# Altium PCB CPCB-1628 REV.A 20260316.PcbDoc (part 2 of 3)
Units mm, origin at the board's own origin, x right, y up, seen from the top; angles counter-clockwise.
Board outline 103 x 58.8 mm, 4 copper layers (Top Layer 1, Layer1, Layer2, Bottom Layer 1), stack 0.603 mm thick; 176 components, 137 nets, 518 pads, 340 vias.
Unrouted connection lines stored in the file: 10.
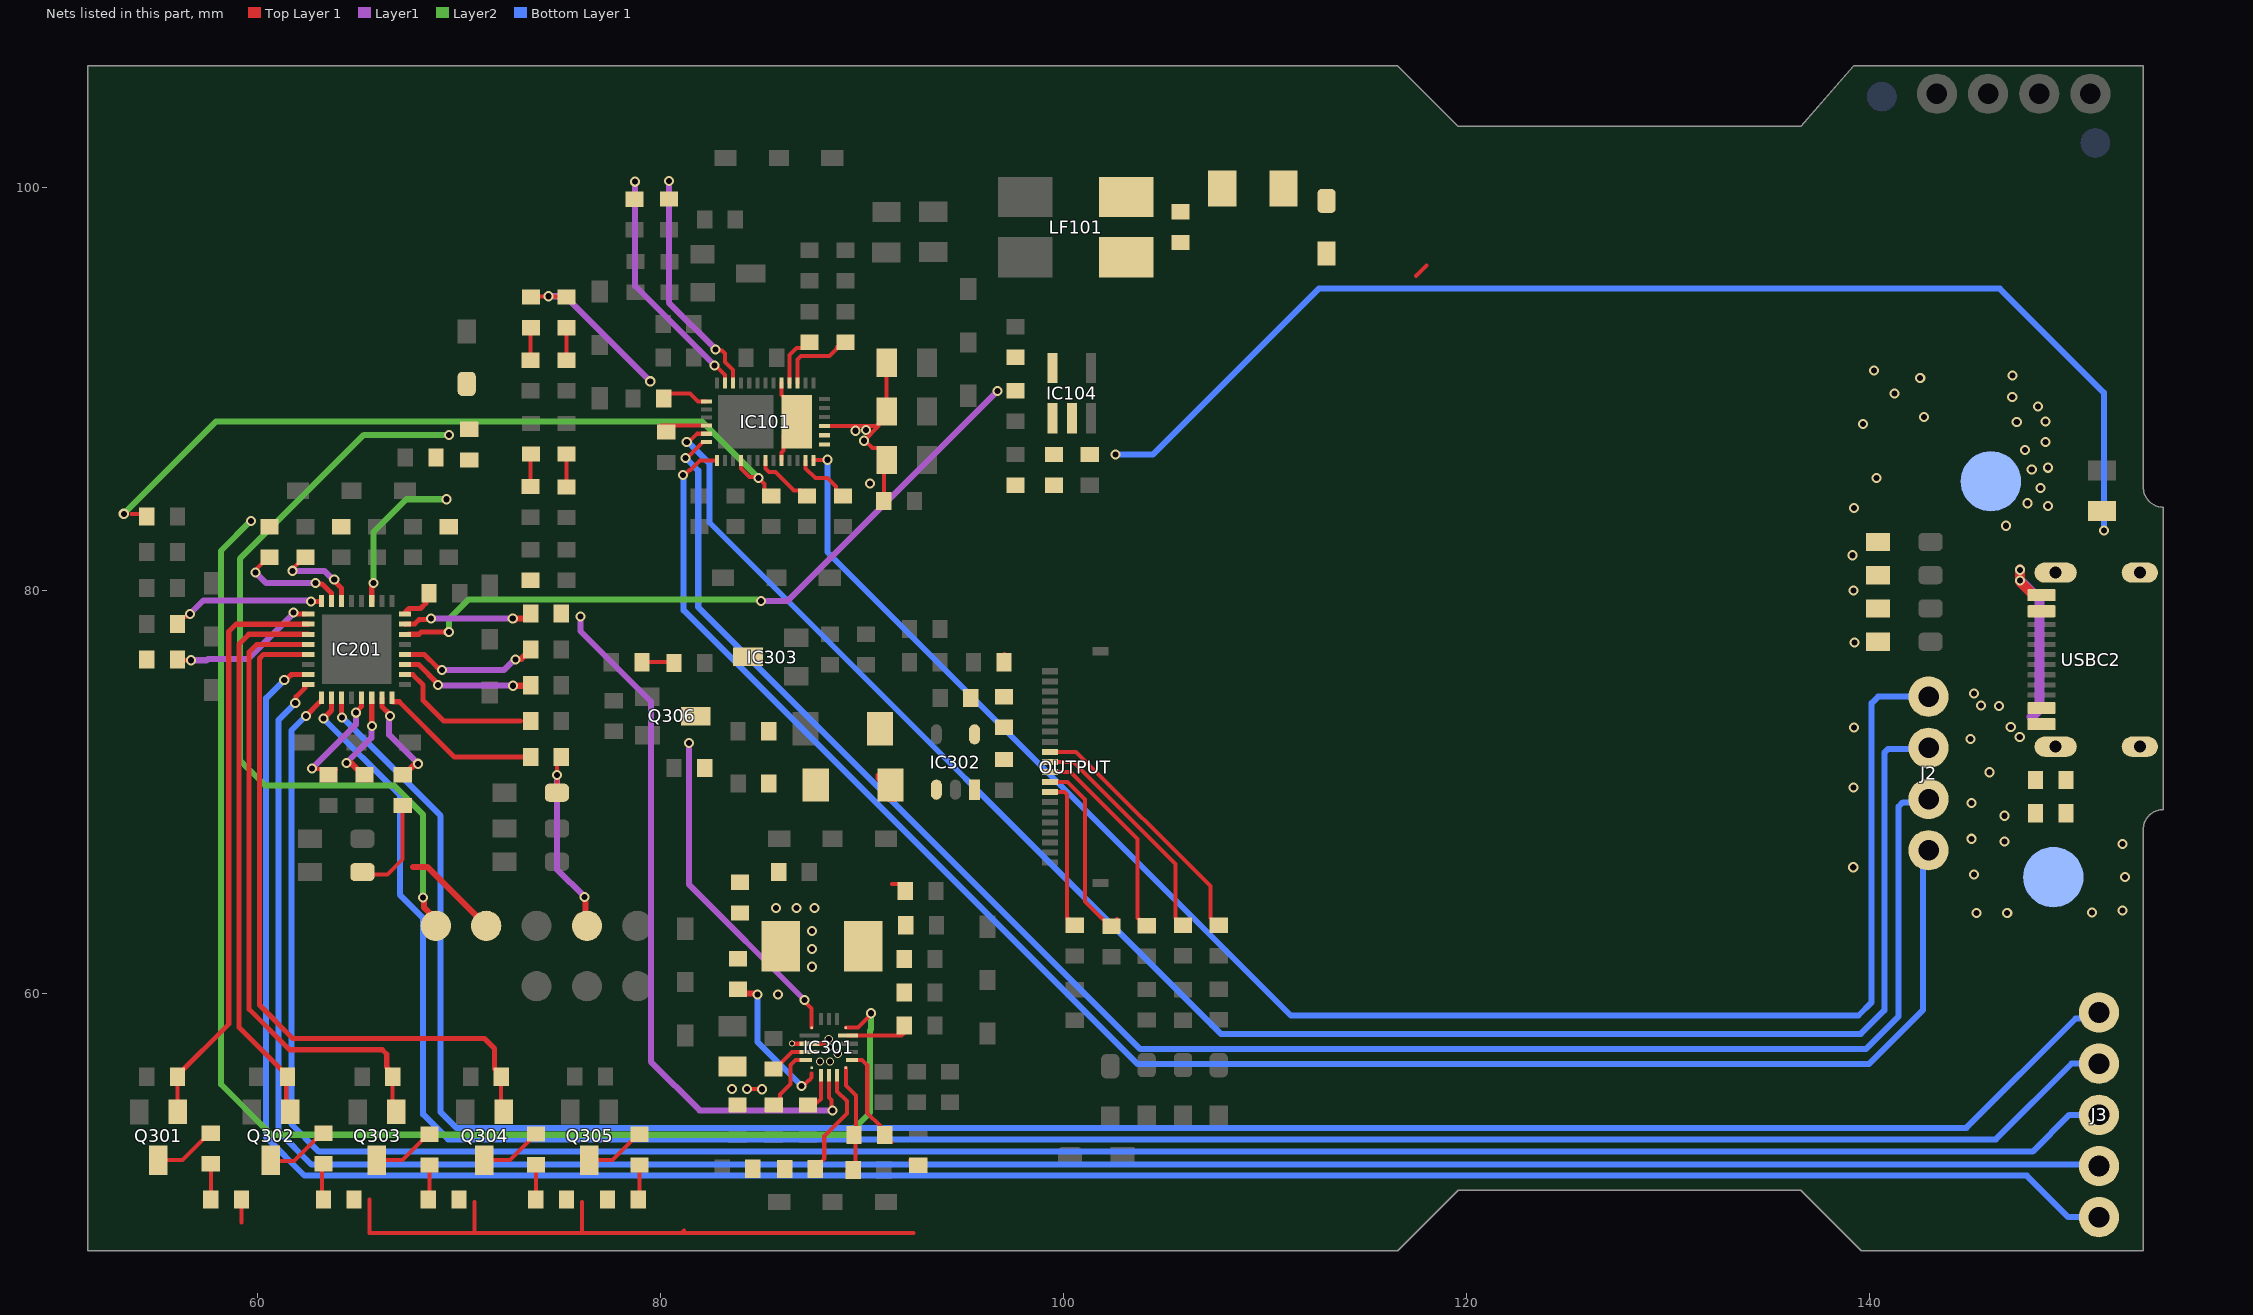
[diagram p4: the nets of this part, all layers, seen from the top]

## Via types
v1: diameter 0.5, hole 0.3, Top Layer 1 to Bottom Layer 1, 334 vias
v2: diameter 0.4, hole 0.3, Top Layer 1 to Bottom Layer 1, 5 vias
v3: diameter 0.3, hole 0.2, Top Layer 1 to Bottom Layer 1, 1 vias

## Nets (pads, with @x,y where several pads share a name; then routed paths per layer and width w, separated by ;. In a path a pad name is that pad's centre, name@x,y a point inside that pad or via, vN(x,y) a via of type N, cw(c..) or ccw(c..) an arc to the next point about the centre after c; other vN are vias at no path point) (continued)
INT_TPS25751D: IC101.10 R103.1 R231.1 R234.2 | length 38
  Top Layer 1 w0.2: 53.721,83.82 R231.1@54.61,83.82 ; IC101.10@83.981,86.467 83.981,86.292 83.981,86.068 84.393,85.655 84.779,85.655 v1(84.836,85.598) 85.126,85.308 85.126,84.987 85.279,84.834 R103.1@85.471,84.834
  Layer2 w0.3: v1(53.34,83.82) 57.912,88.392 82.042,88.392 v1(84.836,85.598)
LDO-1V5: C109.1 IC101.4 | length 2.2
  Top Layer 1 w0.2: C109.1@80.01,88.192 IC101.4@82.256,88.192
LDO-3V3: C108.1 IC101.1 R105.2 R109.2 | length 11.4
  Top Layer 1 w0.2: R105.2@73.533,94.615 v1(74.422,94.615) 75.311,94.615 R109.2@75.591,94.335 ; C108.1@80.135,89.535 80.389,89.789 81.432,89.789 81.829,89.392 IC101.1@82.256,89.392
  Layer1 w0.3: v1(74.422,94.615) 75.248,94.615 v1(79.467,90.396)
LED_GREEN1: IC101.5 J2.2 | length 89.6
  Top Layer 1 w0.2: v1(81.28,87.376) 81.361,87.376 81.777,87.792 IC101.5@82.256,87.792
  Bottom Layer 1 w0.2: v1(81.28,87.376) v1@81.358,87.376
  Bottom Layer 1 w0.3: v1@81.358,87.376 82.403,86.331 82.403,85.911 82.407,85.907 82.407,83.388 107.785,58.01 139.544,58.01 140.716,59.182 140.716,71.96 140.892,72.136 J2.2@142.539,72.136
LED_GREEN2: IC101.6 J2.3 | length 90.5
  Top Layer 1 w0.2: v1(81.218,86.591) 81.28,86.591 82.081,87.392 IC101.6@82.256,87.392
  Bottom Layer 1 w0.2: 81.903,85.598 81.903,85.698
  Bottom Layer 1 w0.3: v1(81.218,86.591) 81.849,85.96 81.849,85.598 81.849,79.187 103.787,57.249 139.799,57.249 141.427,58.877 141.427,69.291 141.634,69.498 142.745,69.498 J2.3@142.909,69.662
LED_GREEN3: IC101.7 J2.4 | length 88.7
  Top Layer 1 w0.2: v1(81.099,85.742) 81.181,85.742 81.425,85.987 81.468,85.987 81.948,86.467 IC101.7@82.781,86.467
  Bottom Layer 1 w0.3: v1(81.099,85.742) 81.128,85.714 81.128,79.033 103.656,56.505 139.944,56.505 142.636,59.197 142.636,66.85 J2.4@142.909,67.122
LED_GREEN4: IC101.19 J2.1 | length 84.7
  Top Layer 1 w0.2: IC101.19@87.581,86.467 87.581,86.484 88.249,86.484 v1(88.266,86.501)
  Bottom Layer 1 w0.3: v1(88.266,86.501) 88.266,81.914 111.259,58.921 139.433,58.921 140.081,59.569 140.081,74.422 140.401,74.742 J2.1@142.909,74.742
LED_GREEN5: 
LED_GREEN6: 
LED_RED1: IC201.15 J3.5 | length 117
  Top Layer 1 w0.2: IC201.15@62.495,75.837 IC201.15@62.497,75.839
  Top Layer 1 w0.254: v1(61.303,75.567) 61.369,75.567 61.633,75.831 61.674,75.831 61.682,75.839 62.494,75.839 IC201.15@62.495,75.837
  Bottom Layer 1 w0.3: v1(61.303,75.567) 60.409,74.674 60.409,52.875 62.31,50.974 147.781,50.974 149.845,48.91 J3.5@151.367,48.91
LED_RED2: IC201.16 J3.4 | length 114
  Top Layer 1 w0.254: v1(61.849,74.422) 61.896,74.469 61.896,74.738 62.324,75.166 62.324,75.337 62.326,75.339 IC201.16@62.497,75.339
  Bottom Layer 1 w0.3: v1(61.849,74.422) 61.022,73.595 61.022,53.151 62.645,51.528 151.224,51.528 J3.4@151.367,51.384
LED_RED3: IC201.17 J3.3 | length 112.8
  Top Layer 1 w0.2: IC201.17@63.147,74.514 IC201.17@63.147,74.689
  Top Layer 1 w0.254: v1(62.38,73.786) 63.109,74.514 IC201.17@63.147,74.514
  Bottom Layer 1 w0.3: v1(62.38,73.786) 61.662,73.067 61.662,53.527 63.023,52.166 148.074,52.166 149.899,53.991 J3.3@151.367,53.99
LED_RED4: IC201.18 J3.2 | length 108.1
  Top Layer 1 w0.254: v1(63.246,73.66) 63.647,74.061 IC201.18@63.647,74.689
  Bottom Layer 1 w0.3: v1(63.246,73.66) 67.037,69.869 67.037,64.916 68.199,63.754 68.199,54.013 69.438,52.773 146.245,52.773 150.002,56.53 J3.2@151.367,56.53
LED_RED5: 
LED_RED6: 
LED_WHITE: IC201.19 J3.1 | length 107.6
  Top Layer 1 w0.2: v1@64.15,73.739 v1(64.172,73.716)
  Top Layer 1 w0.254: v1@64.15,73.739 IC201.19@64.15,74.686
  Bottom Layer 1 w0.3: v1(64.172,73.716) 69.065,68.824 69.065,54.125 69.85,53.34 144.78,53.34 150.214,58.774 151.071,58.774 J3.1@151.367,59.07
NetC104_1: C104.1 C105.1 USBC2.1 USBC2.2 USBC2.3 USBC2.4
NetC116_1: C116.1 IC104.5
NetC201_1: 
NetC202_1: 
NetC203_1: 
NetC204_1: 
NetC205_1: 
NetC206_1: 
NetC207_1: 
NetC208_1: 
NetC209_1: 
NetC210_1: 
NetC211_1: 
NetC212_1: 
NetC216_2: C216.2 IC201.32 | length 1.8
  Top Layer 1 w0.254: IC201.32@67.319,78.951 67.49,79.121 68.072,79.121 68.329,79.378 68.329,79.63 C216.2@68.582,79.883
NetC303_1: C303.1 C304.1 IC301.17 | length 2.1
  Top Layer 1 w0.2: C304.1@85.707,56.263 85.707,56.32 85.93,56.543 85.936,56.543 86.511,57.118 IC301.17@87.377,57.118
NetC305_1: C305.1 IC301.1 | length 7.4
  Top Layer 1 w0.2: v1(86.976,55.424) 87.057,55.424 87.358,55.725 87.36,55.725 87.477,55.843 87.477,56.036
  Top Layer 1 w0.3: C305.1@83.827,60.218 84.045,60.001 84.747,60.001 v1(84.785,59.963)
  Bottom Layer 1 w0.3: v1(84.785,59.963) 84.785,57.615 v1(86.976,55.424)
NetC305_2: C305.2 IC301.16 L301.1 R306.2 | length 1.8
  Top Layer 1 w0.2: v3@86.611,57.518 88.12,57.518 88.288,57.349 v2(88.329,57.349)
  other v1: 85.811,59.963 87.503,61.341 87.485,62.23 87.485,63.119 85.707,64.262 86.723,64.262 87.612,64.262
  other v2: 87.884,56.642 88.392,56.642 88.773,57.023 88.327,57.758
  other v3: 86.502,57.528
NetC306_1: C306.1 IC301.2 | length 1.9
  Top Layer 1 w0.2: C306.1@87.243,54.597 87.751,54.597 87.934,54.78 IC301.2@87.934,55.955
NetC307_2: C307.2 R306.1
NetC319_1: C319.1 C320.2 D301.2 D302.2 IC303.3 | length 0.2
  Top Layer 1 w0.2: C319.1@85.456,73.029 C319.1@85.469,73.016 ; D301.2@87.374,70.174 D301.2@87.374,70.349
NetF101_1: F101.1 pad.1@146.001,85.434 USBC2.A4B9 USBC2.B4A9 ZD1.2
  other v1: 146.408,74.284 145.51,74.316 145.164,74.894 146.747,83.226 148.844,84.201 147.817,84.344 148.463,85.09 148.03,86.009 148.844,86.106 147.701,86.995 148.717,87.376 147.284,88.376 148.717,88.392 148.336,89.154 147.063,89.623 147.066,90.678
NetIC101_13: IC101.13 R115.2 | length 3
  Top Layer 1 w0.2: IC101.13@85.181,86.467 85.181,86.068 85.357,85.892 85.685,85.892 86.59,84.987 86.969,84.987 R115.2@87.249,84.707
NetIC101_15: IC101.0@86.741,88.392 IC101.15 IC101.30 | length 4.5
  Top Layer 1 w0.2: IC101.15@85.981,86.467 85.981,86.866 86.076,86.961 86.076,87.727 IC101.0@86.741,88.392 86.741,88.952 85.981,89.712 IC101.30@85.981,90.317
NetIC101_18: IC101.18 R104.1 | length 2.9
  Top Layer 1 w0.2: IC101.18@87.181,86.467 87.181,86.068 87.658,85.591 88.27,85.591 88.677,85.184 88.677,84.987 88.83,84.834 R104.1@89.027,84.834
NetIC101_28: IC101.28 R116.2 | length 3.9
  Top Layer 1 w0.2: IC101.28@86.781,90.317 86.781,91.473 86.959,91.651 88.358,91.651 88.737,92.03 88.737,92.1 89.017,92.38 R116.2@89.087,92.38
NetIC101_29: IC101.29 R117.1 | length 2.6
  Top Layer 1 w0.2: IC101.29@86.381,90.317 86.381,91.694 86.738,92.051 87.026,92.051 R117.1@87.306,92.331
NetIC101_36: IC101.36 R120.1 | length 11.5
  Top Layer 1 w0.2: v1(82.708,91.979) 82.766,91.922 83.032,91.922 83.181,91.773 83.181,91.355 83.581,90.955 IC101.36@83.581,90.317
  Layer1 w0.3: v1(80.391,100.33) 80.391,94.297 v1(82.708,91.979)
NetIC101_37: IC101.37 R119.1 | length 11.9
  Top Layer 1 w0.2: v1(82.659,91.18) 82.717,91.18 83.181,90.716 IC101.37@83.181,90.317
  Layer1 w0.3: v1(78.712,100.299) 78.712,95.127 v1(82.659,91.18)
NetIC102_4: C121.2 IC104.2 NTC101.2 R114.1 | length 61.5
  Top Layer 1 w0.2: R114.1@99.431,86.758 R114.1@99.501,86.758
  Bottom Layer 1 w0.3: v1@102.556,86.754 104.407,86.754 112.649,94.996 146.45,94.996 151.609,89.837 v1(151.609,82.99)
  other v1: 102.549,86.76
NetIC201_6: IC201.6 R228.1 | length 4.4
  Top Layer 1 w0.2: v1(61.722,80.991) 61.779,81.048 61.779,81.155 62.287,81.663 R228.1@62.357,81.663
  Top Layer 1 w0.254: v1(63.785,80.554) 63.785,80.488 64.145,80.128 64.145,79.491 IC201.6@64.147,79.489
  Layer1 w0.3: v1(61.722,80.991) 63.294,80.991 63.731,80.554 v1(63.785,80.554)
NetIC201_7: IC201.7 R232.1 | length 5.7
  Top Layer 1 w0.2: v1(59.887,80.899) 59.945,80.956 59.945,81.099 60.509,81.663 R232.1@60.579,81.663
  Top Layer 1 w0.254: v1(62.865,80.391) 62.912,80.344 63.18,80.344 63.645,79.878 63.645,79.491 IC201.7@63.647,79.489
  Layer1 w0.3: v1(59.887,80.899) 60.395,80.391 v1(62.865,80.391)
NetIC201_8: IC201.8 R233.1 | length 7.7
  Top Layer 1 w0.2: R233.1@56.005,78.359 56.005,78.429 56.285,78.709 56.404,78.709 56.54,78.845 v1(56.621,78.845) ; IC201.8@63.131,79.473 IC201.8@63.147,79.489
  Top Layer 1 w0.254: v1(62.624,79.473) IC201.8@63.131,79.473
  Layer1 w0.3: v1(56.621,78.845) 57.292,79.516 62.527,79.516 62.57,79.473 v1(62.624,79.473)
NetIC201_9: IC201.9 R234.1 | length 7.4
  Top Layer 1 w0.2: R234.1@56.005,76.581 56.035,76.551 v1(56.672,76.551)
  Top Layer 1 w0.254: v1(61.767,78.916) 61.833,78.916 61.908,78.841 IC201.9@62.324,78.841
  Layer1 w0.2: v1@61.767,78.874 v1(61.767,78.916)
  Layer1 w0.3: v1(56.672,76.551) 57.453,76.551 57.522,76.621 59.513,76.621 v1@61.767,78.874
NetIC201_21: IC201.21 R235.1 | length 5.9
  Top Layer 1 w0.2: v1(62.676,71.176) 62.707,71.144 63.533,71.144 R235.1@63.691,70.985 ; v1(64.858,73.947) v1@64.891,73.947
  Top Layer 1 w0.254: R235.1@63.691,70.985 63.823,71.117 R235.1@63.847,71.117 ; v1@64.891,73.947 64.891,74.015 65.145,74.269 65.145,74.687 IC201.21@65.147,74.689
  Layer1 w0.3: v1(62.676,71.176) 64.858,73.358 v1(64.858,73.947)
NetIC201_22: IC201.22 R236.2 | length 5.2
  Top Layer 1 w0.254: R236.2@65.348,70.737 65.348,70.864 R236.2@65.601,71.117 ; IC201.22@65.649,74.516 65.649,73.307 v1(65.668,73.288)
  Top Layer 1 w0.3: v1(64.386,71.452) 64.424,71.414 64.658,71.414 65.208,70.864 R236.2@65.278,70.864
  Layer1 w0.3: v1(64.386,71.452) 65.63,72.696 65.63,73.25 v1(65.668,73.288)
NetIC201_23: IC201.23 R226.2 | length 5
  Top Layer 1 w0.254: IC201.23@66.147,74.689 66.149,74.689 66.153,74.685 66.157,74.685 66.157,74.245 66.548,73.854 v1(66.548,73.787)
  Top Layer 1 w0.3: R226.2@67.183,70.864 67.253,70.864 67.764,71.375 67.907,71.375 v1(67.945,71.413)
  Layer1 w0.254: v1@66.511,73.75 v1(66.548,73.787)
  Layer1 w0.3: v1@66.511,73.75 66.511,72.847 v1(67.945,71.413)
NetIC201_24: IC201.24 R227.1 | length 8.2
  Top Layer 1 w0.2: IC201.24@66.647,74.689 66.647,74.514 IC201.24@66.672,74.489
  Top Layer 1 w0.254: IC201.24@66.672,74.489 67.01,74.489 69.744,71.755 R227.1@73.535,71.755
NetIC201_26: IC201.26 R238.1 | length 7.1
  Top Layer 1 w0.254: IC201.26@67.297,75.839 67.299,75.837 67.686,75.837 68.199,75.324 68.199,74.549 69.218,73.53 73.026,73.53
NetIC201_27: IC201.27 R239.1 | length 6.7
  Top Layer 1 w0.254: IC201.27@67.297,76.339 67.978,76.339 68.939,75.378 v1(68.939,75.326)
  Top Layer 1 w0.3: v1(72.658,75.286) 73.51,75.286 R239.1@73.535,75.311
  Layer1 w0.3: v1(68.939,75.326) 68.959,75.306 72.638,75.306 v1(72.658,75.286)
NetIC201_28: IC201.28 R240.1 | length 7
  Top Layer 1 w0.254: IC201.28@67.297,76.839 68.255,76.839 68.895,76.2 68.943,76.2 69.066,76.077 v1(69.133,76.077)
  Top Layer 1 w0.3: v1(72.771,76.581) 72.809,76.619 73.065,76.619 73.235,76.789 73.305,76.789 73.535,77.019 R240.1@73.535,77.089
  Layer1 w0.3: v1(69.133,76.077) 72.213,76.077 72.717,76.581 v1(72.771,76.581)
NetIC201_31: IC201.31 R242.1 | length 6.7
  Top Layer 1 w0.254: IC201.31@67.297,78.339 67.299,78.341 67.754,78.341 ; 67.754,78.347 67.768,78.347 67.78,78.359 ; 67.781,78.359 67.988,78.566 68.533,78.566 v1(68.58,78.613) ; v1(72.644,78.613) 72.711,78.613 v1@72.785,78.539 ; R242.1@73.362,78.624 73.535,78.797 R242.1@73.535,78.867
  Top Layer 1 w0.3: v1@72.655,78.624 R242.1@73.362,78.624
  Layer1 w0.3: v1(68.58,78.613) v1(72.644,78.613)
NetIC301_4: IC301.4 R301.2 | length 5.5
  Top Layer 1 w0.2: R301.2@87.664,51.308 87.664,51.378 88.103,51.817 88.103,52.943 89.223,54.063 89.223,54.669 88.734,55.158 IC301.4@88.734,55.955
NetIC301_14: IC301.14 Q306.3 R303.1 R304.1 R305.1 | length 18.4
  Top Layer 1 w0.2: R305.1@79.056,76.455 R303.1@80.766,76.455 ; R304.1@82.165,71.136 R304.1@82.165,71.206 ; v1(87.122,59.69) 87.122,59.622 87.477,59.267 IC301.14@87.477,58.318
  Layer1 w0.3: v1(81.385,72.45) 81.385,65.427 v1(87.122,59.69)
NetIC302_4: IC302.4 R325.1 R326.1 R327.2 | length 0.4
  Top Layer 1 w0.2: R326.1@97.026,76.454 97.039,76.454 R326.1@97.039,76.849
NetOUTPUT_1: OUTPUT.10 R329.2 | length 10.3
  Top Layer 1 w0.2: OUTPUT.10@99.3,71.005 100.316,71.005 103.639,67.682 103.639,63.753 103.665,63.753 104.036,63.382 R329.2@104.106,63.382
NetOUTPUT_2: OUTPUT.11 R330.2 | length 11
  Top Layer 1 w0.2: OUTPUT.11@99.3,71.505 99.304,71.501 100.462,71.501 105.529,66.434 R330.2@105.529,63.769
  Top Layer 1 w0.254: R330.2@106.228,63.641 106.228,63.649 106.233,63.653 R330.2@106.24,63.653
NetOUTPUT_3: OUTPUT.8 R331.2 | length 7.6
  Top Layer 1 w0.2: OUTPUT.8@99.3,70.005 100.032,70.005 100.149,69.888 100.149,63.789 100.187,63.751 100.187,63.672 100.467,63.392 R331.2@100.537,63.392
NetOUTPUT_4: OUTPUT.12 R332.2 | length 12.8
  Top Layer 1 w0.2: OUTPUT.12@99.3,72.005 100.6,72.005 107.261,65.344 R332.2@107.261,63.767 ; R332.2@107.331,63.682 107.611,63.402 R332.2@107.681,63.402 R332.2@107.634,63.45
NetOUTPUT_6: OUTPUT.9 R333.2 | length 9.4
  Top Layer 1 w0.2: OUTPUT.9@99.3,70.505 99.304,70.501 100.178,70.501 101.05,69.629 101.05,64.567 101.886,63.73 101.909,63.73 102.29,63.35 R333.2@102.36,63.35 ; R333.2@102.358,63.369 102.638,63.649 R333.2@102.638,63.707
NetQ201_1: 
NetQ202_1: 
NetQ203_1: 
NetQ204_1: 
NetQ205_1: 
NetQ206_1: 
NetQ207_1: 
NetQ208_1: 
NetQ209_1: 
NetQ210_1: 
NetQ211_1: 
NetQ212_1: 
NetQ301_1: Q301.3 R311.1 | length 3.2
  Top Layer 1 w0.2: Q301.3@55.043,51.746 56.25,51.746 57.588,53.084 R311.1@57.658,53.084
NetQ302_1: Q302.3 R314.1 | length 3.1
  Top Layer 1 w0.2: Q302.3@60.63,51.696 61.787,51.696 63.114,53.022 R314.1@63.184,53.022
NetQ303_1: Q303.3 R317.2 | length 3.1
  Top Layer 1 w0.2: Q303.3@65.901,51.746 67.171,51.746 68.448,53.022 R317.2@68.518,53.022
NetQ304_1: Q304.3 R320.2 | length 3.1
  Top Layer 1 w0.2: Q304.3@71.234,51.746 72.506,51.746 73.717,52.957 R320.2@73.787,52.957
NetQ305_1: Q305.3 R323.2 | length 3
  Top Layer 1 w0.2: Q305.3@76.441,51.746 77.585,51.746 78.862,53.022 R323.2@78.932,53.022
NetQ306_1: 
NetQ306_3: 
NetR105_1: R105.1 R106.2 | length 1.7
  Top Layer 1 w0.2: R106.2@73.533,91.44 R105.1@73.533,93.095
NetR107_1: R107.1 R108.2 | length 1.5
  Top Layer 1 w0.2: R108.2@73.533,85.215 R107.1@73.533,86.747
NetR109_1: R109.1 R110.2 | length 1.7
  Top Layer 1 w0.2: R110.2@75.311,91.44 R109.1@75.311,93.095
NetR111_1: R111.1 R112.2 | length 1.5
  Top Layer 1 w0.2: R112.2@75.311,85.217 R111.1@75.311,86.745
NetR113_1: 
NetR113_2: R113.1 R114.2
NetR301_1: R301.1 R302.2
NetR310_1: R310.1 R311.2 | length 1.8
  Top Layer 1 w0.2: R311.2@57.658,51.564 57.658,49.786 R310.1@57.66,49.784
NetR313_1: R313.1 R314.2 | length 1.7
  Top Layer 1 w0.2: R313.1@63.123,49.784 63.184,49.845 R314.2@63.184,51.502
NetR316_1: R316.1 R317.1 | length 1.9
  Top Layer 1 w0.2: R316.1@68.455,49.657 68.518,49.72 R317.1@68.518,51.502
NetR319_1: R319.1 R320.1 | length 1.8
  Top Layer 1 w0.2: R320.1@73.787,51.437 73.787,49.659 R319.1@73.789,49.657
NetR322_1: R322.1 R323.1 | length 1.8
  Top Layer 1 w0.2: R323.1@78.862,51.502 R323.1@78.932,51.502 78.932,49.847 R322.1@78.869,49.784
NetR327_1: R327.1 R328.2 | length 0
  Top Layer 1 w0.2: R328.2@97.015,71.514 R328.2@97.028,71.528
NORMAL: IC201.11 Q302.1 R315.2 | length 27.8
  Top Layer 1 w0.2: R315.2@61.163,56.23 61.186,56.23 61.404,56.012 R315.2@61.404,55.88 ; R315.2@61.404,55.818 61.404,54.339 Q302.1@61.595,54.148
  Top Layer 1 w0.254: 59.543,77.831 59.055,77.343 59.055,58.338 R315.2@61.163,56.23 ; 59.543,77.839 IC201.11@62.497,77.839
NRST: C215.2 IC201.3 R225.1 R244.1 | length 8
  Top Layer 1 w0.2: IC201.3@65.647,79.489 IC201.3@65.672,79.514 ; v1@65.672,80.339 v1(65.724,80.391) ; R225.1@69.399,83.183 R225.1@69.469,83.183 R225.1@69.539,83.183
  Top Layer 1 w0.254: IC201.3@65.647,79.489 65.647,80.247 65.724,80.324 v1(65.724,80.391)
  Layer2 w0.3: v1(65.724,80.391) 65.724,82.906 67.36,84.542 v1(69.356,84.542)
OTP_DET: IC104.1 IC201.30 R118.1 | length 34.7
  Top Layer 1 w0.254: IC201.30@67.47,77.839 67.978,77.839 68.085,77.946 69.456,77.946 v1(69.469,77.959)
  Layer1 w0.3: v1(84.963,79.502) 86.291,79.502 v1(96.707,89.918)
  Layer2 w0.3: v1(69.469,77.959) 69.469,78.587 70.45,79.568 84.755,79.568 84.783,79.54 84.925,79.54 v1(84.963,79.502)
PG: IC301.3 R242.2 R243.1 | length 35.4
  Top Layer 1 w0.2: IC301.3@88.334,55.955 88.334,54.86 88.458,54.736 88.458,54.267 v1(88.516,54.21)
  Layer1 w0.3: v1(76.001,78.72) 76.001,78.004 79.502,74.503 79.502,56.628 81.92,54.21 v1(88.516,54.21)
PPHV: C110.1 C111.1 C112.1 C113.1 C301.1 C302.1 IC101.20 IC101.21 IC101.22 IC301.18 | length 15.2
  Top Layer 1 w0.2: v1(84.276,55.274) 84.283,55.267 85.005,55.267 v1(85.013,55.26) ; C302.1@85.58,54.483 85.631,54.483 85.911,54.763 85.911,55.006 86.426,55.522 86.426,56.468 86.676,56.718 IC301.18@87.186,56.718 ; IC101.22@88.106,88.167 90.182,88.167 90.668,88.167 C111.1@90.998,88.497 ; C113.1@91.063,84.455 91.063,86.349 C112.1@91.202,86.488 91.202,86.688 90.802,87.088 90.491,87.088 90.135,87.444 v1(90.068,87.444) 90.08,87.444 90.802,88.165 90.802,88.301 C111.1@90.998,88.497 ; C111.1@91.202,88.565 C110.1@91.202,91.314 ; C111.1@90.998,88.497 91.134,88.497 C111.1@90.998,88.497
  other v1: 83.525,55.281 90.377,85.333 89.657,87.94 90.182,87.983
PRE_COOL: IC201.10 Q301.1 R312.2 | length 29
  Top Layer 1 w0.2: R312.2@56.007,55.88 56.007,54.15 Q301.1@56.008,54.148
  Top Layer 1 w0.254: R312.2@56.007,55.88 56.007,55.95 58.547,58.49 58.547,77.981 58.905,78.339 IC201.10@62.497,78.339
PRE_WARM: IC201.12 Q303.1 R318.2 | length 31.4
  Top Layer 1 w0.2: R318.2@66.675,55.88 66.675,54.339 Q303.1@66.867,54.148
  Top Layer 1 w0.254: 59.944,77.331 59.936,77.331 59.563,76.958 59.563,59.226 61.57,57.219 66.17,57.219 66.388,57.001 66.388,56.355 66.44,56.303 66.44,56.136 R318.2@66.693,55.883 ; 59.944,77.339 IC201.12@62.324,77.339
SGND: C101.2 C104.2 C105.2 LF101.2 pad.1@149.098,65.786 USBC2.A1B12 USBC2.A12B1 ZD1.1 ZD2.1 ZD3.1 ZD5.1 ZD6.1 | length 10
  Top Layer 1 w0.2: 117.477,95.633 117.985,96.141
  Top Layer 1 w0.5: v1(147.445,81.041) 147.445,80.449 148.113,79.781 USBC2.A12B1@148.513,79.781
  Layer1 w0.5: v1(147.447,80.518) 148.405,79.56 148.405,74.11 148.026,73.731
  other v1: 145.288,64.008 146.812,64.008 151.012,64.024 152.527,64.135 152.654,65.786 145.161,65.913 139.17,66.279 152.527,67.437 146.685,67.564 145.034,67.691 146.685,68.834 145.034,69.469 139.194,70.244 145.923,70.993 144.979,72.639 147.434,72.734 139.217,73.219 146.987,73.244 139.232,77.438 139.192,80.01 139.125,81.761 139.208,84.103 140.335,85.598 139.658,88.284 142.687,88.621 141.224,89.789 142.494,90.551 140.208,90.932
STAT: IC301.10 R229.1 R232.2 | length 69
  Top Layer 1 w0.2: R232.2@60.579,83.183 R232.2@60.649,83.183 ; R229.1@64.065,83.183 R229.1@64.135,83.183 ; IC301.10@89.177,58.318 89.777,58.318 90.072,58.613 90.072,58.615 90.425,58.968 v1(90.425,59.032)
  Layer2 w0.3: v1(59.648,83.466) 58.166,81.984 58.166,55.499 60.663,53.002 89.279,53.002 90.374,54.096 90.374,58.182 90.425,58.233 v1(90.425,59.032)
SWCLK: pad.1@76.327,63.373 R227.2 ZD13.2 | length 10
  Top Layer 1 w0.2: ZD13.2@74.833,69.977 74.833,71.533 R227.2@75.055,71.755
  Top Layer 1 w0.3: v1(76.207,64.811) 76.246,64.772 76.246,63.454 pad.1@76.327,63.373
  Layer1 w0.3: v1(74.836,70.856) 74.836,66.182 v1(76.207,64.811)
SWDIO: pad.1@71.327,63.373 R226.1 ZD12.2 | length 9.8
  Top Layer 1 w0.2: ZD12.2@65.054,65.913 66.421,65.913 67.183,66.675 R226.1@67.183,69.196
  Top Layer 1 w0.3: 67.699,66.3 68.4,66.3 pad.1@71.327,63.373
SYS: C308.1 C309.1 C310.1 C315.1 C316.1 D301.1 IC301.9 IC302.1 IC302.3 L301.2 | length 8.9
  Top Layer 1 w0.2: IC301.9@89.277,57.918 91.94,57.918 C308.1@92.061,58.039 ; D301.1@91.129,69.848 D301.1@91.353,69.624 ; D301.1@91.408,69.624 D301.1@91.583,69.624 ; 91.467,65.452 91.721,65.452 91.846,65.452 92.126,65.172 C316.1@92.126,65.102 ; C310.1@92.077,61.722 C310.1@92.077,61.792 ; D301.1@91.089,69.809 90.875,70.023 D301.1@91.256,69.642 ; D301.1@91.089,69.809 D301.1@91.256,69.642 ; D301.1@91.089,69.809 D301.1@91.256,69.642 ; D301.1@91.089,69.809 D301.1@91.256,69.642 ; D301.1@91.089,69.809 D301.1@91.256,69.642 ; D301.1@91.089,69.809 D301.1@91.256,69.642 ; D301.1@91.089,69.809 D301.1@91.256,69.642 ; D301.1@91.089,69.809 D301.1@91.256,69.642 ; D301.1@91.089,69.809 D301.1@91.256,69.642 ; D301.1@91.089,69.809 D301.1@91.256,69.642 ; D301.1@91.089,69.809 D301.1@91.256,69.642 ; D301.1@91.089,69.809 D301.1@91.256,69.642 ; D301.1@90.748,70.675 90.748,70.85 91.074,70.524 91.074,70.349 D301.1@90.748,70.675
TP1: pad.1@68.827,63.373 R244.2 ZD11.2 | length 38.9
  Top Layer 1 w0.3: v1(68.199,64.77) 68.237,64.732 68.237,64.287 68.827,63.698 pad.1@68.827,63.373
  Layer2 w0.3: v1(68.199,64.77) 68.199,68.89 66.929,70.16 66.753,70.336 60.356,70.336 59.105,71.586 59.105,81.584 65.259,87.738 v1(69.491,87.738)
TS: IC301.6 R308.1 R309.2 R310.2 R313.2 R316.2 R319.2 R322.2 | length 38.7
  Top Layer 1 w0.2: 59.18,48.643 R310.2@59.18,49.784 ; 65.53,49.784 65.53,48.135 65.532,48.133 70.739,48.133 ; 70.737,49.657 70.737,48.135 70.739,48.133 ; R319.2@75.029,49.504 R319.2@75.309,49.784 ; 76.071,49.657 76.071,48.135 76.073,48.133 ; 81.151,48.258 81.026,48.133 ; IC301.6@89.477,56.718 89.978,56.718 90.237,56.458 90.237,54.085 90.886,53.436 ; R308.1@91.1,52.986 91.1,52.916 91.38,52.636 R308.1@91.45,52.636 ; R308.1@91.361,53.086 R308.1@91.361,53.156 ; R309.2@92.369,51.717 92.48,51.717 R309.2@92.76,51.437 ; 92.538,48.133 81.026,48.133 ; 70.739,48.133 76.073,48.133 ; 76.073,48.133 81.026,48.133
TS-BIAS: C311.1 IC301.5 R308.2 | length 5.7
  Top Layer 1 w0.2: IC301.5@89.177,56.318 89.177,55.458 89.677,54.958 89.677,52.761 89.665,52.749 C311.1@89.665,51.29 ; C311.1@89.245,51.207 89.37,51.082 C311.1@89.523,51.082 ; C311.1@89.523,51.12 C311.1@89.595,51.191
VBUS: C101.1 F101.2 LF101.1 | length 0.4
  Top Layer 1 w0.2: F101.2@107.857,99.606 F101.2@107.857,99.957
WARM: IC201.13 Q304.1 R321.2 | length 35.4
  Top Layer 1 w0.2: R321.2@72.072,55.818 72.072,54.276 Q304.1@72.199,54.148
  Top Layer 1 w0.254: 60.266,76.831 60.071,76.636 60.071,59.436 61.722,57.785 71.247,57.785 71.744,57.288 71.744,56.277 72.072,55.95 R321.2@72.072,55.88 ; 60.274,76.839 IC201.13@62.324,76.839
pads on no net: "USBC2.A8 SBU1" "USBC2.B8 SBU2" IC101.34 IC101.35 IC104.4 IC201.20 IC201.25 IC301.7 OUTPUT.0 OUTPUT.13

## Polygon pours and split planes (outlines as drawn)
INT_BATT_IC on Top Layer 1 "NONET_L-01_P-001" (hatched Horizontal grid 0.1 track 0.11, pour order 536): 101.093,61.805 101.945,60.952 101.945,59.817 101.104,59.817 101.093,59.828
GND on Top Layer 1 "NONET_L-01_P-001" (hatched Horizontal grid 0.1 track 0.11, remove dead copper, pour order 548): 22 vertices, not listed, extent 52.066,47.85 152.886,105.521
D+ on Top Layer 1 "NONET_L-01_P-001" (hatched Horizontal grid 0.1 track 0.11, remove dead copper, pour order 549): 22 vertices, not listed, extent 52.002,47.914 152.822,105.585
NetOUTPUT_1 on Top Layer 1 "NONET_L-01_P-001" (hatched Horizontal grid 0.1 track 0.11, pour order 540): 104.758,63.81 103.903,63.81 103.704,64.01 103.605,64.01 103.605,62.996 103.609,62.991 104.618,62.991 104.761,63.134
BAT+ on Top Layer 1 "NONET_L-01_P-001" (hatched Horizontal grid 0.1 track 0.11, pour order 542): 19 vertices, not listed, extent 95.675,47.862 114.618,76.454
NetOUTPUT_3 on Top Layer 1 "NONET_L-01_P-001" (hatched Horizontal grid 0.1 track 0.11, pour order 541): 101.16,63.838 100.407,63.838 100.207,64.037 100.108,64.037 100.108,63.023 100.112,63.019 101.132,63.019 101.164,63.05
NetOUTPUT_2 on Top Layer 1 "NONET_L-01_P-001" (hatched Horizontal grid 0.1 track 0.11, pour order 539): 106.542,63.81 105.763,63.81 105.563,64.01 105.464,64.01 105.464,62.996 105.468,62.991 106.506,62.991 106.546,63.031
NetOUTPUT_4 on Top Layer 1 "NONET_L-01_P-001" (hatched Horizontal grid 0.1 track 0.11, pour order 538): 108.167,63.818 107.514,63.818 107.314,64.017 107.215,64.017 107.215,63.003 107.22,62.998 108.136,62.998 108.172,63.033
I2Ct-SCL on Top Layer 1 "NONET_L-01_P-001" (hatched Horizontal grid 0.1 track 0.11, pour order 537): 103.622,62.298 103.622,61.585 103.178,61.141 102.821,61.141 102.788,61.108 102.788,59.817 103.613,59.817
INT_BATT_IC on Top Layer 1 "NONET_L-01_P-001" (hatched Horizontal grid 0.1 track 0.11, pour order 73): 100.052,59.828 100.052,62.318 101.093,62.318 101.093,59.828
I2Ct-SCL on Top Layer 1 "NONET_L-01_P-001" (hatched Horizontal grid 0.1 track 0.11, pour order 74): 103.613,59.817 103.613,62.288 103.632,62.307 104.699,62.307 104.699,59.817
I2Ct-SDA on Top Layer 1 "NONET_L-01_P-001" (hatched Horizontal grid 0.1 track 0.11, pour order 75): 105.369,59.82 105.369,62.31 106.585,62.31 106.585,59.82
NetOUTPUT_3 on Top Layer 1 "NONET_L-01_P-001" (hatched Horizontal grid 0.1 track 0.11, pour order 118): 100.101,63.022 100.101,63.81 101.061,63.81 101.061,63.025
NetOUTPUT_1 on Top Layer 1 "NONET_L-01_P-001" (hatched Horizontal grid 0.1 track 0.11, pour order 119): 103.617,63.005 103.617,63.793 104.576,63.793 104.576,63.008
NetOUTPUT_2 on Top Layer 1 "NONET_L-01_P-001" (hatched Horizontal grid 0.1 track 0.11, pour order 120): 105.475,63 105.475,63.788 106.435,63.788 106.435,63.003
INT_BATT_IC on Top Layer 1 "NONET_L-01_P-001" (hatched Horizontal grid 0.1 track 0.11, pour order 315): 101.718,55.726 102.782,55.726 102.934,55.878 102.934,57.427 102.622,57.739 102.118,57.739 101.718,57.339
I2Ct-SCL on Top Layer 1 "NONET_L-01_P-001" (hatched Horizontal grid 0.1 track 0.11, pour order 316): 104.66,57.109 103.672,57.109 103.565,57.002 103.565,55.362 103.832,55.096 104.336,55.096 104.66,55.419
I2Ct-SDA on Top Layer 1 "NONET_L-01_P-001" (hatched Horizontal grid 0.1 track 0.11, pour order 317): 106.402,57.103 105.414,57.103 105.303,56.992 105.303,55.361 105.574,55.09 106.151,55.09 106.402,55.342
ATTACH on Top Layer 1 "NONET_L-01_P-001" (hatched Horizontal grid 0.1 track 0.11, pour order 389): 108.174,57.094 107.186,57.094 107.149,57.056 107.149,55.278 107.346,55.081 107.851,55.081 108.174,55.404
ATTACH on Top Layer 1 "NONET_L-01_P-001" (hatched Horizontal grid 0.1 track 0.11, pour order 400): 107.206,59.769 107.206,62.24 107.292,62.326 108.426,62.326 108.426,59.769
NetOUTPUT_6 on Top Layer 1 "NONET_L-01_P-001" (hatched Horizontal grid 0.1 track 0.11, pour order 471): 101.849,62.946 101.849,63.734 102.937,63.734 102.937,62.949
NetF101_1 on Top Layer 1 "NONET_L-01_P-001" (hatched Horizontal grid 0.1 track 0.11, remove dead copper, pour order 192): 24 vertices, not listed, extent 118.931,73.934 149.161,102.475
SGND on Top Layer 1 "NONET_L-01_P-001" (hatched Horizontal grid 0.1 track 0.11, remove dead copper, pour order 533): 30 vertices, not listed, extent 101.683,63.483 153.035,97.623
LED_GREEN4 on Top Layer 1 "NONET_L-01_P-001" (hatched Horizontal grid 0.1 track 0.11, pour order 523): 141.775,75.789 141.775,73.665 143.891,73.665 143.891,75.789
LED_GREEN3 on Top Layer 1 "NONET_L-01_P-001" (hatched Horizontal grid 0.1 track 0.11, pour order 495): 141.841,68.157 141.841,66.033 143.957,66.033 143.957,68.157
LED_GREEN2 on Top Layer 1 "NONET_L-01_P-001" (hatched Horizontal grid 0.1 track 0.11, pour order 494): 141.85,70.694 141.85,68.57 143.966,68.57 143.966,70.694
LED_GREEN1 on Top Layer 1 "NONET_L-01_P-001" (hatched Horizontal grid 0.1 track 0.11, pour order 493): 141.841,73.24 141.841,71.116 143.957,71.116 143.957,73.24
LED_RED1 on Top Layer 1 "NONET_L-01_P-001" (hatched Horizontal grid 0.1 track 0.11, pour order 491): 150.343,49.995 150.343,47.87 152.459,47.87 152.459,49.995
LED_RED2 on Top Layer 1 "NONET_L-01_P-001" (hatched Horizontal grid 0.1 track 0.11, pour order 490): 150.321,52.49 150.321,50.365 152.437,50.365 152.437,52.49
LED_RED3 on Top Layer 1 "NONET_L-01_P-001" (hatched Horizontal grid 0.1 track 0.11, pour order 489): 150.321,55.06 150.321,52.935 152.437,52.935 152.437,55.06
LED_RED4 on Top Layer 1 "NONET_L-01_P-001" (hatched Horizontal grid 0.1 track 0.11, pour order 488): 150.311,57.609 150.311,55.484 152.426,55.484 152.426,57.609
BAT+ on Top Layer 1 "NONET_L-01_P-001" (hatched Horizontal grid 0.1 track 0.11, pour order 468): 89.891,57.568 95.205,57.568 95.623,57.15 96.768,57.15 97.186,57.568 101.028,57.568 101.028,54.737 95.932,54.737 95.252,55.417 90.645,55.417 90.645,56.802 90.424,57.023
"BSL UART_TX" on Top Layer 1 "NONET_L-01_P-001" (hatched Horizontal grid 0.1 track 0.11, pour order 479): 74.178,66.044 74.617,66.044 74.949,65.711 75.144,65.711 75.463,66.029 75.463,66.045
TS on Top Layer 1 "NONET_L-01_P-001" (hatched Horizontal grid 0.1 track 0.11, pour order 467): 90.7,53.503 91.505,53.503 91.505,52.82 92.732,51.593 92.425,51.593 91.483,52.536 90.7,52.536
TS-BIAS on Top Layer 1 "NONET_L-01_P-001" (hatched Horizontal grid 0.1 track 0.11, pour order 466): 89.173,53.426 89.365,53.426 89.647,53.708 89.659,53.696 89.75,53.696 89.963,53.484 89.963,50.772 89.173,50.772
+3.2V on Top Layer 1 "NONET_L-01_P-001" (hatched Horizontal grid 0.1 track 0.11, pour order 465): 93.446,72.6 93.446,79.292 94.165,80.01 95.885,80.01 95.885,76.073 95.123,76.073 94.487,75.437 94.487,74.343 93.876,73.731 93.876,72.6
NetR327_1 on Top Layer 1 "NONET_L-01_P-001" (hatched Horizontal grid 0.1 track 0.11, pour order 464): 96.537,73.65 96.537,71.205 97.531,71.205 97.531,73.648
NetIC302_4 on Top Layer 1 "NONET_L-01_P-001" (hatched Horizontal grid 0.1 track 0.11, pour order 463): 17 vertices, not listed, extent 94.987,72.48 97.498,76.945
SYS on Top Layer 1 "NONET_L-01_P-001" (hatched Horizontal grid 0.1 track 0.11, pour order 462): 30 vertices, not listed, extent 89.05,57.867 95.782,71.422
NetC319_1 on Top Layer 1 "NONET_L-01_P-001" (hatched Horizontal grid 0.1 track 0.11, pour order 461): 22 vertices, not listed, extent 83.528,69.446 91.578,77.235
+VBUS on Top Layer 1 "NONET_L-01_P-001" (hatched Horizontal grid 0.1 track 0.11, pour order 460): 86.397,74.061 87.269,74.061 88.011,74.803 89.281,74.803 89.535,74.549 89.535,74.369 87.914,72.748 87.914,72.269 86.366,72.269 86.36,72.263
NetIC301_14 on Top Layer 1 "NONET_L-01_P-001" (hatched Horizontal grid 0.1 track 0.11, pour order 41): 81.786,70.698 81.786,71.608 80.685,72.709 80.685,75.282 79.952,76.015 78.64,76.015 78.64,76.849 81.024,76.849 81.024,75.905 82.567,74.362 82.567,70.693
+3.3V on Top Layer 1 "NONET_L-01_P-001" (hatched Horizontal grid 0.1 track 0.11, pour order 458): 81.722,78.15 81.325,78.15 81.026,77.851 81.026,77.216 81.553,77.216 81.722,77.047
+1.8V on Top Layer 1 "NONET_L-01_P-001" (hatched Horizontal grid 0.1 track 0.11, pour order 456): 85.981,77.131 85.981,78.21 88.87,78.21 89.789,79.129 89.789,81.096 89.304,81.581 89.307,81.584 92.921,81.584 90.633,79.296 90.633,77.131
+1.8V on Top Layer 1 "NONET_L-01_P-001" (hatched Horizontal grid 0.1 track 0.11, pour order 455): 90.424,83.058 93.218,83.058 94.556,84.396 94.556,87.19 96.189,88.823 98.062,88.823 98.062,86.392 96.017,86.392 95.539,85.914 95.539,84.236 92.887,81.584 90.424,81.584
NetC306_1 on Top Layer 1 "NONET_L-01_P-001" (hatched Horizontal grid 0.1 track 0.11, pour order 81): 87.864,55.064 87.658,54.858 86.866,54.858 86.866,54.098 87.831,54.098 87.864,54.132
BQ25622_CE_N on Top Layer 1 "NONET_L-01_P-001" (hatched Horizontal grid 0.1 track 0.11, pour order 40): 79.973,75.269 78.613,75.269 77.927,75.954 77.927,77.143 77.133,77.143 77.133,74.258 77.23,74.161 79.984,74.161
+3.3V on Top Layer 1 "NONET_L-01_P-001" (hatched Horizontal grid 0.1 track 0.11, pour order 86): 81.722,75.944 81.722,78.15 82.851,78.15 82.851,75.946
ATTACH on Top Layer 1 "NONET_L-01_P-001" (hatched Horizontal grid 0.1 track 0.11, pour order 91): 74.689,77.559 76.124,77.559 76.729,78.164 76.729,79.721 76.268,80.182 74.857,80.182 74.857,80.877 76.603,80.877 77.289,80.191 77.289,78.107 75.675,76.493 74.685,76.493
+1.8V on Top Layer 1 "NONET_L-01_P-001" (hatched Horizontal grid 0.1 track 0.11, pour order 19): 22 vertices, not listed, extent 63.611,81.189 90.424,83.693
NetR107_1 on Top Layer 1 "NONET_L-01_P-001" (hatched Horizontal grid 0.1 track 0.11, pour order 8): 73.09,87.227 74.091,87.227 74.091,84.803 74.071,84.783 73.074,84.783
NetR111_1 on Top Layer 1 "NONET_L-01_P-001" (hatched Horizontal grid 0.1 track 0.11, pour order 10): 74.82,87.204 75.82,87.204 75.82,84.8 75.801,84.781 74.804,84.781
ADCIN1 on Top Layer 1 "NONET_L-01_P-001" (hatched Horizontal grid 0.1 track 0.11, pour order 11): 72.997,90.385 73.997,90.385 73.997,87.946 73.978,87.927 72.981,87.927
NetR105_1 on Top Layer 1 "NONET_L-01_P-001" (hatched Horizontal grid 0.1 track 0.11, pour order 12): 73.033,93.448 74.034,93.448 74.034,91.09 74.014,91.071 73.018,91.071
NetR109_1 on Top Layer 1 "NONET_L-01_P-001" (hatched Horizontal grid 0.1 track 0.11, pour order 13): 74.789,93.442 75.79,93.442 75.79,91.084 75.771,91.064 74.774,91.064
LDO-3V3 on Top Layer 1 "NONET_L-01_P-001" (hatched Horizontal grid 0.1 track 0.11, pour order 344): 73.059,95.006 75.788,95.006 75.813,94.981 75.813,94.137 73.07,94.137
OTP_DET on Top Layer 1 "NONET_L-01_P-001" (hatched Horizontal grid 0.1 track 0.11, pour order 345): 99.636,87.861 99.636,89.293 98.606,90.322 96.424,90.322 96.424,89.584 96.494,89.513 98.461,89.513 99.092,88.882 99.092,87.861
NetIC102_4 on Top Layer 1 "NONET_L-01_P-001" (hatched Horizontal grid 0.1 track 0.11, pour order 346): 100.203,89.245 100.203,87.714 99.625,87.136 98.862,87.136 98.862,86.393 102.903,86.393 102.903,87.167 101.211,87.167 100.584,87.793 100.584,89.249 100.58,89.253
NetR113_2 on Top Layer 1 "NONET_L-01_P-001" (hatched Horizontal grid 0.1 track 0.11, pour order 347): 97.106,85.695 99.979,85.695 99.979,84.831 99.986,84.824 97.108,84.824
NetC116_1 on Top Layer 1 "NONET_L-01_P-001" (hatched Horizontal grid 0.1 track 0.11, pour order 348): 97.122,92.008 97.122,91.181 98.4,91.181 99.218,90.362 99.638,90.362 99.638,91.768 99.412,91.994
NetR301_1 on Top Layer 1 "NONET_L-01_P-001" (hatched Horizontal grid 0.1 track 0.11, pour order 14): 84.06,50.776 84.06,51.776 86.551,51.776 86.639,51.688 86.639,50.759
PPHV on Top Layer 1 "NONET_L-01_P-001" (hatched Horizontal grid 0.1 track 0.11, pour order 79): 86.33,55.53 83.131,55.53 83.131,54.058 86.044,54.058 86.33,54.344
NetC303_1 on Top Layer 1 "NONET_L-01_P-001" (hatched Horizontal grid 0.1 track 0.11, pour order 82): 86.058,56.686 84.514,56.686 84.272,56.927 82.798,56.927 82.798,55.85 86.058,55.85
NetIC301_4 on Top Layer 1 "NONET_L-01_P-001" (hatched Horizontal grid 0.1 track 0.11, pour order 123): 87.294,51.804 88.082,51.804 88.082,50.844 87.297,50.844
NetC305_2 on Top Layer 1 "NONET_L-01_P-001" (hatched Horizontal grid 0.1 track 0.11, pour order 201): 21 vertices, not listed, extent 87.659,56.452 88.991,58.234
